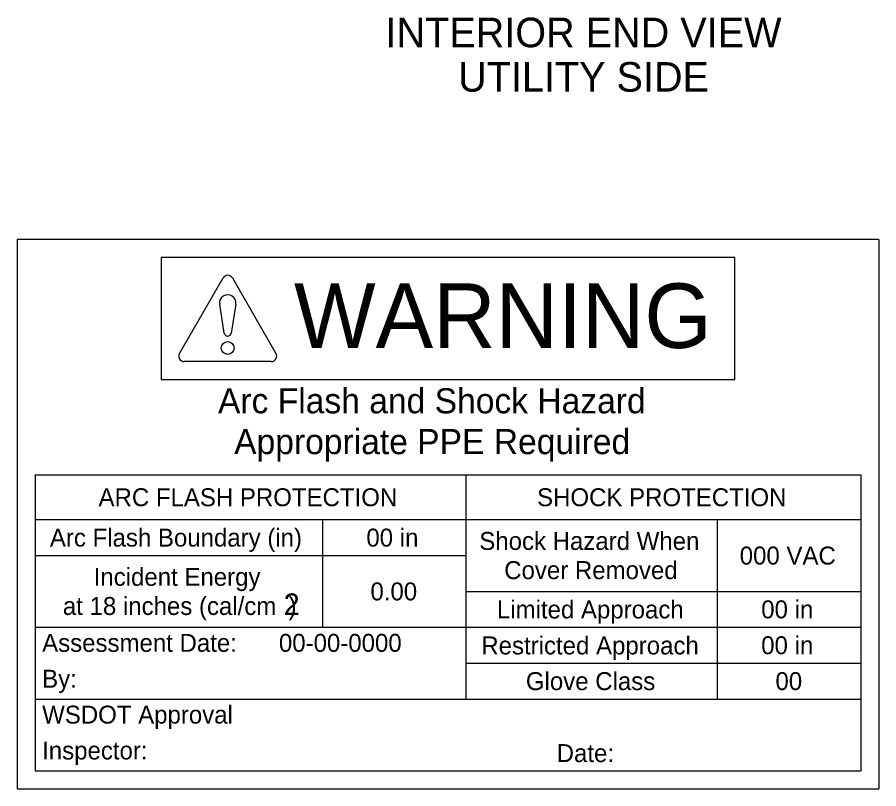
# Model space of a CAD drawing. Extents: x 99862 to 103680, y 99470 to 105076.
# Drawn here: x 101012.5 to 101492.5, y 103979.8 to 104409.8 of the extents above; entities that cross this region are included whole.
import ezdxf

# ---------------------------------------------------------------- set-up
doc = ezdxf.new("R2010")
doc.units = 0
doc.layers.add('Level 20', color=7, linetype='Continuous')
doc.layers.add('Level 35', color=7, linetype='Continuous')

msp = doc.modelspace()

# ---------------------------------------------------------------- linework, layer by layer
at = {"layer": 'Level 35'}
for p, q in [((101012.48, 104285.97), (101012.48, 103979.76)), ((101492.48, 104285.97), (101012.48, 104285.97)), ((101492.48, 104285.97), (101492.48, 103979.76)), ((101127.8, 104233.76), (101125.27, 104249.86)), ((101134.25, 104249.86), (101131.72, 104233.76)), ((101022.48, 104154.76), (101022.48, 103989.76)), ((101022.48, 104154.76), (101482.48, 104154.76)), ((101262.48, 104154.76), (101262.48, 104029.76)), ((101482.48, 104154.76), (101482.48, 103989.76)), ((101022.48, 104129.76), (101482.48, 104129.76)), ((101182.48, 104129.76), (101182.48, 104069.76)), ((101402.48, 104129.76), (101402.48, 104029.76)), ((101022.48, 104109.76), (101262.48, 104109.76)), ((101262.48, 104089.76), (101482.48, 104089.76)), ((101022.48, 104069.76), (101262.48, 104069.76)), ((101262.48, 104069.76), (101482.48, 104069.76)), ((101262.48, 104049.76), (101482.48, 104049.76)), ((101022.48, 104029.76), (101262.48, 104029.76)), ((101262.48, 104029.76), (101482.48, 104029.76)), ((101022.48, 103989.76), (101482.48, 103989.76)), ((101012.48, 103979.76), (101492.48, 103979.76))]:
    msp.add_line(p, q, dxfattribs=at)
msp.add_lwpolyline([(101092.62, 104207.9), (101412.35, 104207.9), (101412.35, 104275.97), (101092.62, 104275.97)], close=True, dxfattribs=at)
for points in [[(101102.87, 104222.4), (101127.16, 104264.47)], [(101132.36, 104264.47), (101156.65, 104222.4)], [(101154.05, 104217.9), (101105.47, 104217.9)]]:
    msp.add_lwpolyline(points, dxfattribs=at)
msp.add_circle((101129.74, 104225.43), 3.58, dxfattribs=at)
for centre, radius, start, end in [((101129.76, 104262.97), 3, 30, 150), ((101129.76, 104250.57), 4.54, 351.09, 188.91), ((101129.76, 104234.07), 1.99, 188.91, 351.09), ((101105.47, 104220.9), 3, 150, 270), ((101154.05, 104220.9), 3, 270, 30)]:
    msp.add_arc(centre, radius, start, end, dxfattribs=at)

# ---------------------------------------------------------------- texts
at = {"layer": 'Level 20'}
for s, p in [('INTERIOR END VIEW', (101217.64, 104393.06)), ('UTILITY SIDE', (101258.12, 104368.31))]:
    msp.add_text(s, height=16.5, dxfattribs=at).set_placement(p)
at = {"layer": 'Level 35'}
for s, height, p in [('WARNING', 36, (101166.7, 104225.43)), ('Arc Flash and Shock Hazard', 14, (101124.34, 104189.02)), ('Appropriate PPE Required', 14, (101133.34, 104166.27)), ('ARC FLASH PROTECTION', 10, (101057.78, 104137.26)), ('SHOCK PROTECTION', 10, (101302.11, 104137.26)), ('Arc Flash Boundary (in)', 10, (101030.68, 104114.76)), ('00 in', 10, (101207, 104114.76)), ('Shock Hazard When', 10, (101269.92, 104112.89)), ('000 VAC', 10, (101415.02, 104104.76)), ('Incident Energy', 10, (101055.08, 104092.89)), ('Cover Removed', 10, (101283.8, 104096.64)), ('0.00', 10, (101209.27, 104084.76)), ('2', 12, (101160.94, 104076.64)), ('at 18 inches (cal/cm', 10, (101037.91, 104076.64)), (')', 10, (101163.66, 104076.64)), ('Limited Approach', 10, (101279.73, 104074.72)), ('00 in', 10, (101427, 104074.76)), ('Assessment Date:', 10, (101026.37, 104056.1)), ('00-00-0000', 10, (101158.28, 104056.1)), ('Restricted Approach', 10, (101271.05, 104054.65)), ('00 in', 10, (101427, 104054.76)), ('By:', 10, (101026.37, 104036.1)), ('Glove Class', 10, (101295.87, 104034.76)), ('00', 10, (101434.93, 104034.76)), ('WSDOT Approval', 10, (101026.37, 104016.1)), ('Inspector:', 10, (101026.37, 103996.1)), ('Date:', 10, (101313.04, 103994.65))]:
    msp.add_text(s, height=height, dxfattribs=at).set_placement(p)

doc.saveas('drawing.dxf')
